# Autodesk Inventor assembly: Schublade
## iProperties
Created: 2008-11
Part Number: Schublade
Project: Anlage
Description: Benennung
Document SubType Name: Baugruppe
Designer: GEIKON
SaveDate: 2005-04-14
SaveTime: 20:44
TotalMass: 0 kg
TotalVolume: 0 mm^3
Author: GEIKON
Revision Number: 00
